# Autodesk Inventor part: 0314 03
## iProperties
Created: 2016-04
Part Number: 0314 03
Checked By: TraceParts S.A.
Catalog Web Link: www.traceparts.com
Description: Chassis plug acc. to IEC 61076-2-106, IP 68, with threaded joint and solder terminals, for front mounting - 0314 03
Vendor: LUMBERG
Document SubType Name: Modeling
Designer: TraceParts
Company: TraceParts S.A.
Title: Chassis plug acc. to IEC 61076-2-106, IP 68, with threaded joint and solder terminals, for front mounting - 0314 03
Author: TraceParts
REFERENCE: 0314 03
poles: 3
SUPPLIER: LUMBERG
DESIGN: Chassis plug acc. to IEC 61076-2-106, IP 68, with threaded joint and solder terminals, for front mounting - 0314 03
ue: 50
TraceParts.PartStatus: Published
TraceParts.PartNumber: 10-10112014-103001
TraceParts.PartLanguage: en
TraceParts.InstanceId: 10-10112014-103001B8G6JYKBA7MYJ0NJ4FK09SI0K
TraceParts.PartTitle: 0314
TRACEPARTS: TRACEPARTS
TraceParts.PartVersion: 1.0.7
TraceParts.ClassPath: LUMBERG:/F_LUMBERG/LUMBERG.020/10-10112014-103001
